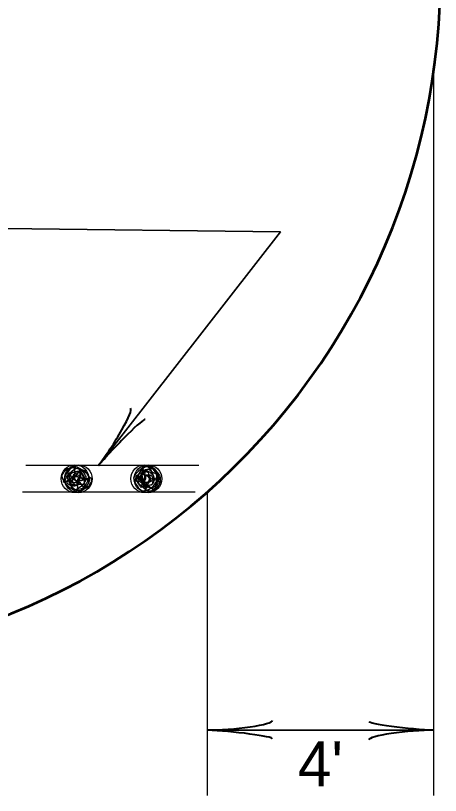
# Model space of a CAD drawing. Extents: x -133 to 547, y -328 to 112.
# Drawn here: x 325.15 to 343.97, y -97.03 to -62.46 of the extents above; entities that cross this region are included whole.
import ezdxf

# ---------------------------------------------------------------- set-up
doc = ezdxf.new("R2010")
doc.units = 0
doc.header["$LTSCALE"] = 0.8
doc.layers.add('1', color=7, linetype='Continuous', lineweight=35)
doc.layers.add('4', color=7, linetype='Continuous', lineweight=25)

msp = doc.modelspace()

# ---------------------------------------------------------------- linework, layer by layer
at = {"layer": '1', "lineweight": 25}
for p, q in [((343.6778, -97.0253), (343.6778, -64.8886)), ((333.2628, -82.4024), (325.6128, -82.4025)), ((333.1133, -83.5817), (325.4633, -83.5816)), ((333.6604, -97.0253), (333.6604, -83.5655))]:
    msp.add_line(p, q, dxfattribs=at)
at = {"layer": '1'}
msp.add_line((333.6604, -94.1312), (343.6778, -94.1312), dxfattribs=at)
msp.add_lwpolyline([(328.8222, -82.4025), (336.8819, -72.048), (324.6463, -71.895)], dxfattribs=at)
at = {"layer": '1', "lineweight": 53}
msp.add_arc((313.4133, -60.6809), 30.5557, 269.84467, 11.96498, dxfattribs=at)
at = {"layer": '1', "lineweight": 40}
for centre, major_axis, ratio, start_param, end_param in [((329.2745, -81.3717), (-0.9736, -1.5051), 0.122415, 0.8963533, 3.1415927), ((329.6775, -81.6483), (-1.2175, -1.2782), 0.07063, 3.1407148, 5.41811), ((334.7516, -93.8549), (-1.7857, -0.1562), 0.122415, 0.8963533, 3.1415927), ((342.5573, -93.9196), (1.7565, -0.1757), 0.07063, 3.1407148, 5.41811), ((334.7809, -94.3428), (-1.7565, 0.1757), 0.07063, 3.1407148, 5.41811), ((342.5866, -94.4075), (1.7857, 0.1562), 0.122415, 0.8963533, 3.1415927)]:
    msp.add_ellipse(centre, major_axis=major_axis, ratio=ratio, start_param=start_param, end_param=end_param, dxfattribs=at)
at = {"layer": '1', "lineweight": 25}
for points in [[(327.8333, -83.4617), (328.1333, -83.2517), (328.2833, -82.9517), (328.1933, -82.7417), (327.8633, -82.5317), (327.5333, -82.5317), (327.2032, -82.8617), (327.4133, -83.2517), (327.8333, -83.4617), (328.0133, -83.3416), (328.1633, -83.2517), (328.2233, -82.9817), (328.0133, -82.6217), (327.8933, -82.4717), (327.4733, -82.7117), (327.5333, -83.0117), (327.5933, -83.1917), (327.7133, -83.2517), (327.8933, -83.2517), (327.9833, -83.0717), (328.0133, -82.7417), (327.8033, -82.7417), (327.6533, -82.7117), (327.5333, -82.8917), (327.7433, -83.1617), (327.9233, -83.0417), (327.9532, -82.9217), (327.7433, -82.8917), (327.7733, -82.8316), (327.3233, -83.1617), (327.7133, -82.4417), (327.8034, -82.8617), (328.0734, -82.5917), (328.3733, -83.0117), (327.7433, -82.8917), (327.8633, -83.2817), (327.4433, -83.1917), (327.7433, -82.8917)], [(327.9828, -82.5224), (328.2828, -82.7324), (328.4328, -83.0324), (328.3428, -83.2424), (328.0128, -83.4524), (327.6828, -83.4524), (327.3528, -83.1224), (327.5628, -82.7324), (327.9828, -82.5224), (328.1628, -82.6425), (328.3128, -82.7324), (328.3728, -83.0024), (328.1628, -83.3624), (328.0428, -83.5124), (327.6228, -83.2724), (327.6828, -82.9724), (327.7428, -82.7924), (327.8628, -82.7324), (328.0428, -82.7324), (328.1328, -82.9124), (328.1628, -83.2424), (327.9528, -83.2424), (327.8028, -83.2724), (327.6828, -83.0924), (327.8928, -82.8224), (328.0728, -82.9424), (328.1028, -83.0624), (327.8928, -83.0924), (327.9228, -83.1525), (327.4728, -82.8224), (327.8628, -83.5424), (327.9529, -83.1224), (328.2229, -83.3924), (328.5228, -82.9724), (327.8928, -83.0924), (328.0128, -82.7024), (327.5928, -82.7924), (327.8928, -83.0924)], [(330.8633, -83.5217), (331.1933, -83.3717), (331.4033, -83.0417), (331.3433, -82.6817), (330.9533, -82.4417), (330.5933, -82.6517), (330.3833, -82.9517), (330.4433, -83.1617), (330.8633, -83.5217), (331.0733, -83.2817), (331.2533, -83.1917), (331.2833, -83.0117), (331.0732, -82.5917), (330.8633, -82.6217), (330.7133, -82.7417), (330.4733, -82.8917), (330.6533, -83.2517), (330.8933, -83.3116), (331.0433, -83.1917), (331.1333, -83.0117), (331.0733, -82.8317), (331.0133, -82.7117), (330.7133, -82.8017), (330.7733, -83.0117), (330.7733, -83.1317), (331.0133, -83.1317), (331.0733, -82.9517), (330.7433, -82.8317), (330.6833, -82.8617), (330.4133, -83.1317), (330.8033, -82.5617), (330.7133, -82.8317), (331.1633, -82.5317), (331.3733, -83.0417), (330.7433, -82.8317), (330.7133, -83.3717), (330.6233, -83.2517), (330.7433, -82.8317)], [(331.0128, -82.4624), (331.3428, -82.6124), (331.5528, -82.9424), (331.4928, -83.3024), (331.1028, -83.5424), (330.7428, -83.3323), (330.5328, -83.0324), (330.5928, -82.8224), (331.0128, -82.4624), (331.2228, -82.7024), (331.4028, -82.7924), (331.4328, -82.9724), (331.2227, -83.3924), (331.0128, -83.3624), (330.8628, -83.2424), (330.6228, -83.0924), (330.8028, -82.7324), (331.0428, -82.6725), (331.1928, -82.7924), (331.2828, -82.9724), (331.2228, -83.1524), (331.1628, -83.2724), (330.8628, -83.1824), (330.9228, -82.9724), (330.9228, -82.8524), (331.1628, -82.8524), (331.2228, -83.0324), (330.8928, -83.1524), (330.8328, -83.1224), (330.5628, -82.8524), (330.9528, -83.4224), (330.8628, -83.1524), (331.3128, -83.4524), (331.5228, -82.9424), (330.8928, -83.1524), (330.8628, -82.6124), (330.7728, -82.7324), (330.8928, -83.1524)]]:
    msp.add_spline(points, degree=3, dxfattribs=at)
at = {"layer": '4'}
for centre in [(327.7852, -82.9913), (327.9347, -82.9928), (330.8704, -82.9915), (331.0199, -82.9926)]:
    msp.add_circle(centre, 0.615, dxfattribs=at)

# ---------------------------------------------------------------- texts
at = {"layer": '1'}
msp.add_text("4'", height=2, dxfattribs=at).set_placement((337.6545, -96.6251))

doc.saveas('drawing.dxf')
